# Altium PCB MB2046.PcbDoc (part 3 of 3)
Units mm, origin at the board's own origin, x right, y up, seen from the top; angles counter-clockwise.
Board outline 70 x 82.5 mm, 2 copper layers (Top Layer, Bottom Layer), stack 1.47 mm thick; 179 components, 148 nets, 719 pads, 862 vias.
Unrouted connection lines stored in the file: 135.
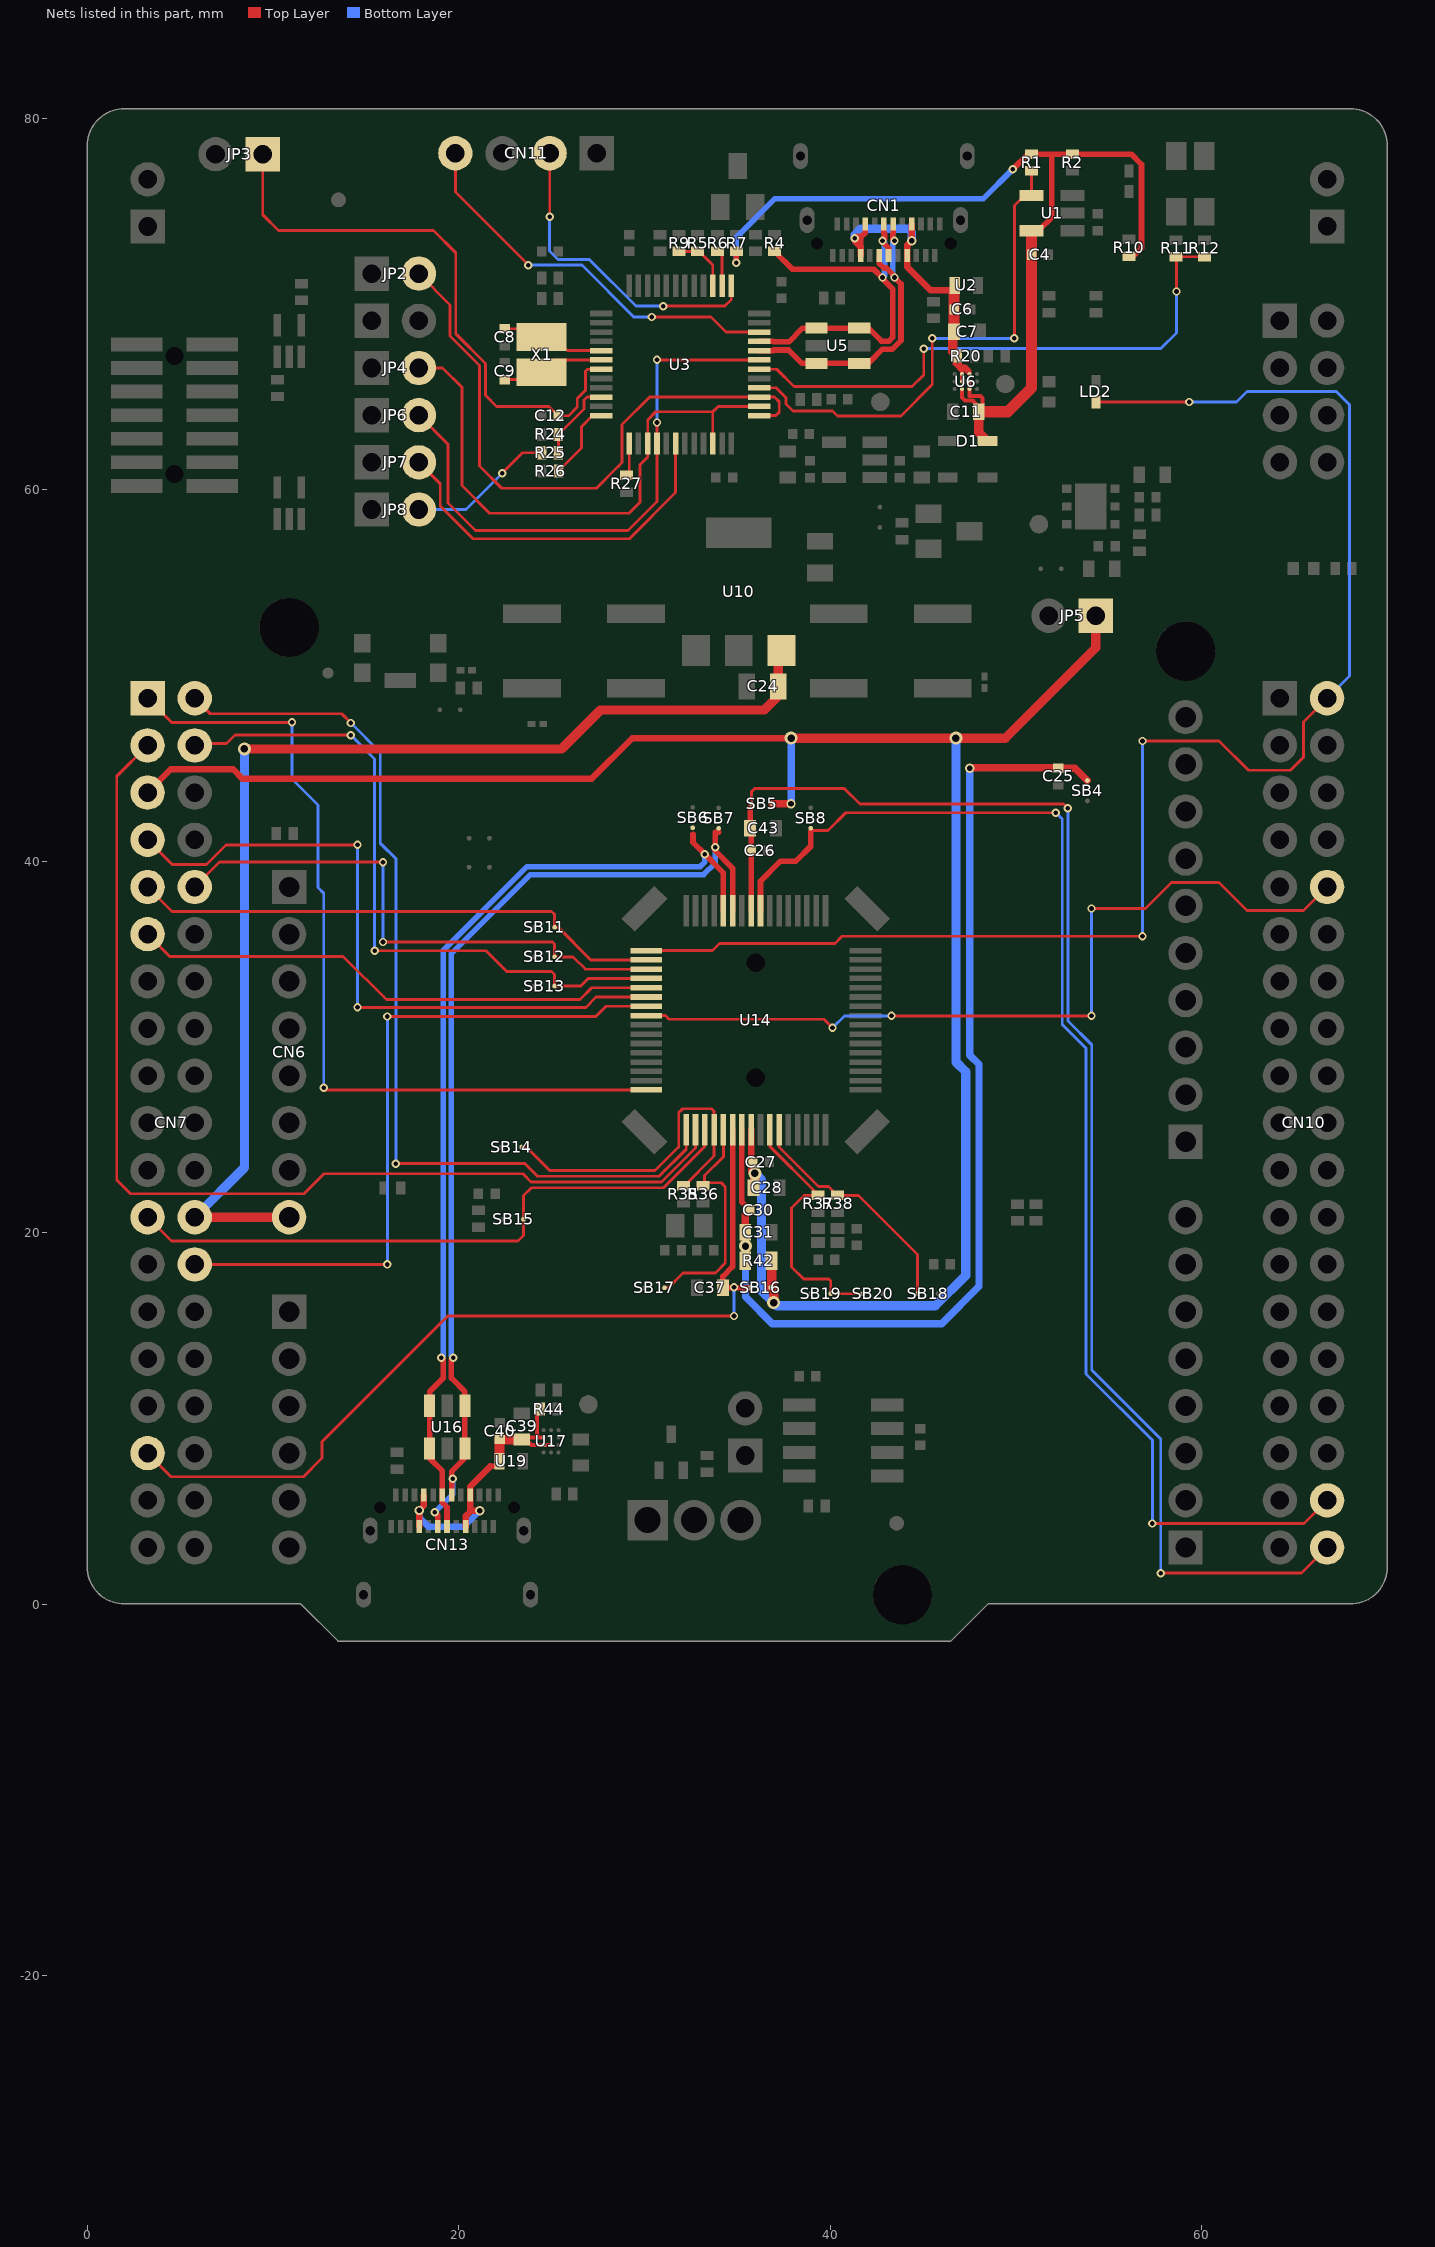
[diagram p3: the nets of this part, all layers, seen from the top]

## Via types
v1: diameter 0.45, hole 0.25, Top Layer to Bottom Layer, tented both sides, 830 vias
v2: diameter 0.7, hole 0.4, Top Layer to Bottom Layer, tented both sides, 21 vias
v3: diameter 0.5, hole 0.3, Top Layer to Bottom Layer, tented both sides, 11 vias

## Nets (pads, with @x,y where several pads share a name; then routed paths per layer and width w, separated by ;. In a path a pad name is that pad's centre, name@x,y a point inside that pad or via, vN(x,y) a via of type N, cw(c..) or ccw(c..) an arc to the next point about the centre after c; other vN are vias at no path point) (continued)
PC9: CN10.2 LD2.2 U14.49 | length 81.3
  Top Layer w0.152: U14.49@30.099,35.183 33.658,35.183 34.042,35.568 40.255,35.568 40.645,35.957 v1(56.813,35.957) ; LD2.2@54.305,64.708 59.318,64.708 v1(59.327,64.718) ; v1@56.818,46.467 60.933,46.467 62.51,44.89 64.778,44.89 65.48,45.592 65.48,47.497 CN10.2@66.751,48.768
  Bottom Layer w0.152: v1(56.813,35.957) v1(56.813,46.467) ; v1(59.327,64.718) 61.873,64.718 62.435,65.28 67.243,65.28 67.954,64.568 67.954,49.971 CN10.2@66.751,48.768
PC10: CN7.1 U14.64 | length 46.2
  Top Layer w0.152: CN7.1@3.251,48.768 4.554,47.465 v1@11.027,47.465 ; v1(12.729,27.8) 12.846,27.683 U14.64@30.099,27.683
  Bottom Layer w0.152: v1(11.027,47.477) 11.027,44.415 12.431,43.012 12.431,38.572 12.736,38.267 12.736,27.807 v1(12.729,27.8) v1@12.693,27.8
PC11: CN7.2 U14.1 | length 51.2
  Top Layer w0.152: CN7.2@5.791,48.768 6.628,47.931 13.702,47.931 v1(14.198,47.435) ; v1(16.618,23.714) 23.558,23.715 24.241,23.032 30.791,23.032 32.249,24.49 U14.1@32.249,25.533
  Bottom Layer w0.152: v1(14.198,47.435) 15.779,45.853 15.779,40.966 16.618,40.128 v1(16.618,23.714)
PC12: CN7.3 U14.2 | length 57.9
  Top Layer w0.152: CN7.3@3.251,46.228 1.593,44.569 1.593,22.835 2.332,22.095 11.668,22.095 12.74,23.168 23.463,23.168 23.902,22.728 30.917,22.728 32.749,24.559 U14.2@32.749,25.533
PC13: CN7.23 SB15.2 U14.3 | length 34.8
  Top Layer w0.152: CN7.23@3.251,20.828 4.532,19.547 23.2,19.547 23.49,19.837 SB15.2@23.49,20.72 23.49,21.992 23.912,22.415 31.035,22.415 33.249,24.629 U14.3@33.249,25.533
PC14: R35.2 SB14.1 U14.4 | length 18.1
  Top Layer w0.152: SB14.1@23.39,24.605 23.635,24.605 24.904,23.336 30.574,23.336 31.842,24.605 31.842,26.45 32.064,26.671 33.609,26.671 33.749,26.531 U14.4@33.749,25.533 33.749,24.121 R35.2@32.142,22.514
PC15: R36.2 SB17.1 U14.5 | length 12.6
  Top Layer w0.152: SB17.1@31.083,17.03 31.283,17.03 32.085,17.832 33.825,17.832 34.352,18.36 34.352,22.465 34.135,22.682 33.403,22.682 33.234,22.514 33.234,23.072 34.249,24.086 U14.5@34.249,25.533
PD0: CN7.9 SB11.1 U14.50 | length 28.9
  Top Layer w0.152: CN7.9@3.251,38.608 4.564,37.295 25.005,37.295 25.163,37.137 SB11.1@25.163,36.436 25.359,36.436 27.112,34.683 U14.50@30.099,34.683
PD1: CN7.10 SB12.1 U14.51 | length 30.3
  Top Layer w0.152: CN7.10@5.791,38.608 7.128,39.945 v1(15.928,39.945) ; v1@15.929,35.642 25.048,35.642 25.163,35.527 SB12.1@25.163,34.846 26.157,34.846 26.819,34.183 U14.51@30.099,34.183
  Bottom Layer w0.152: v1@15.809,35.643 v1(15.928,35.643) v1(15.928,39.945)
PD2: CN7.4 SB13.1 U14.52 | length 36.8
  Top Layer w0.152: CN7.4@5.791,46.228 5.791,46.328 7.496,46.328 7.95,46.782 v1(14.19,46.782) ; v1(15.475,35.177) 21.473,35.177 22.59,34.06 25.003,34.06 25.163,33.899 SB13.1@25.163,33.274 26.569,33.274 26.978,33.683 U14.52@30.099,33.683
  Bottom Layer w0.152: v1(14.19,46.782) 15.475,45.497 v1(15.475,35.177)
PD3: CN7.11 U14.53 | length 28.6
  Top Layer w0.152: CN7.11@3.251,36.068 4.446,34.873 13.779,34.873 16.107,32.546 26.526,32.546 27.163,33.183 U14.53@30.099,33.183
PD4: CN7.7 U14.54 | length 36.8
  Top Layer w0.152: CN7.7@3.251,41.148 4.582,39.817 6.418,39.817 7.473,40.873 14.557,40.873 v1@14.556,40.875 ; v1(14.556,32.127) 26.845,32.127 27.401,32.683 U14.54@30.099,32.683
  Bottom Layer w0.152: v1(14.556,32.127) v1@14.556,40.875
  other v1: 14.556,40.873
PD5: CN7.26 U14.55 | length 37.9
  Top Layer w0.152: CN7.26@5.791,18.288 v1(16.161,18.288) ; v1(16.161,31.637) 27.377,31.637 27.923,32.183 U14.55@30.099,32.183
  Bottom Layer w0.152: v1(16.161,18.288) v1(16.161,31.637)
PD6: CN10.10 U14.56 | length 44.8
  Top Layer w0.152: U14.56@30.099,31.683 31.134,31.683 31.33,31.488 39.67,31.488 v1(40.127,31.03) ; v1(43.302,31.668) 53.438,31.667 ; 53.462,31.668 v1(54.066,31.667) ; v1(54.067,37.453) 56.973,37.453 58.37,38.85 60.922,38.85 62.438,37.335 65.478,37.335 CN10.10@66.751,38.608
  Bottom Layer w0.152: v1(40.127,31.03) 40.765,31.668 v1(43.302,31.668) ; v1@54.066,37.452 v1(54.066,31.667) v1@54.189,31.667
PD8: CN10.36 SB8.1 U14.40 | length 69.9
  Top Layer w0.152: 38.955,41.607 38.955,41.652 39.885,41.652 40.837,42.605 v1(52.148,42.605) ; CN10.36@66.751,5.588 65.506,4.343 v1@57.339,4.343 ; v1(57.338,4.341) v1@57.339,4.343
  Top Layer w0.3: U14.40@36.249,37.333 36.249,38.914 37.331,39.996 38.151,39.996 38.955,40.801 38.955,41.607
  Bottom Layer w0.152: v1(52.148,42.605) 52.493,42.26 52.493,31.21 53.774,29.928 53.774,12.398 57.349,8.823 57.349,4.33 v1(57.338,4.341)
PD9: C26.2 C43.2 CN10.38 SB5.1 U14.41 | length 77.8
  Top Layer w0.152: C43.2@35.575,41.577 C43.2@35.749,41.403 ; 35.755,42.962 35.755,43.733 35.94,43.917 40.755,43.917 41.602,43.07 52.561,43.07 v1(52.794,42.837) ; v1(57.793,1.667) 65.371,1.667 CN10.38@66.751,3.048
  Top Layer w0.3: U14.41@35.749,37.333 C43.2@35.749,41.363 ; C26.2@35.75,40.57 35.75,41.71 C43.2@35.69,41.77 35.69,42.897 35.755,42.962
  Bottom Layer w0.152: v1(52.794,42.837) 52.797,42.834 52.797,31.393 54.079,30.111 54.079,12.596 57.793,8.882 v1(57.793,1.667)
PF0: R37.2 SB19.1 SB20.2 U14.10 | length 14.4
  Top Layer w0.152: U14.10@36.749,25.533 36.749,24.648 R37.2@39.217,22.181 ; R37.2@39.261,22.181 39.44,22.002 R37.2@39.35,22.002 38.584,22.002 37.918,21.335 37.918,18.152 38.575,17.495 39.925,17.495 40.033,17.388 SB19.1@40.033,16.712 41.723,16.712 SB20.2@41.73,16.705
PF1: R38.2 SB18.1 U14.11 | length 12.9
  Top Layer w0.152: U14.11@37.249,25.533 37.249,24.601 39.365,22.485 39.916,22.485 R38.2@40.4,22.002 41.53,22.002 44.708,18.825 SB18.1@44.708,16.718
PF3/VBAT: C37.1 CN7.33 SB16.2 U14.6 | length 47.7
  Top Layer w0.152: CN7.33@3.251,8.128 4.519,6.86 11.637,6.86 12.645,7.868 12.645,8.74 19.415,15.51 v1(34.82,15.51)
  Top Layer w0.3: C37.1@34.225,17.043 34.225,17.645 34.749,18.169 U14.6@34.749,25.533 ; C37.1@34.431,17.043 SB16.2@35.697,17.043
  Bottom Layer w0.152: v1(34.82,15.51) v1(34.82,17.05)
STLK_LED: R11.1 R12.2 U3.30 | length 30.5
  Top Layer w0.12: R11.1@58.623,72.533 R12.2@60.147,72.533
  Top Layer w0.152: U3.30@36.178,66.482 37.12,66.482 38.06,65.543 44.408,65.543 45.037,66.172 v1(45.037,67.59) ; R11.1@58.623,72.533 58.642,72.514 v1(58.642,70.663)
  Bottom Layer w0.152: v1(45.037,67.59) 57.797,67.59 58.642,68.435 v1(58.642,70.663)
STLK_NRST: C12.2 JP3.1 U3.7 | length 31.4
  Top Layer w0.152: JP3.1@9.45,78.058 9.45,74.8 10.292,73.958 18.637,73.958 19.842,72.753 19.842,68.394 21.439,66.796 21.439,65.078 22.037,64.48 24.862,64.48 C12.2@25.371,63.972 25.907,63.972 26.382,64.448 26.382,64.902 26.832,65.352 26.832,66.367 26.947,66.482 U3.7@27.678,66.482
STLK_OSC_IN: C8.2 U3.5 X1.2 | length 5.7
  Top Layer w0.152: C8.2@22.477,68.656 24.02,68.656 X1.2@24.46,68.216 25.046,67.63 25.702,67.63 25.85,67.482 U3.5@27.678,67.482
STLK_OSC_OUT: C9.1 U3.6 X1.1 | length 5.6
  Top Layer w0.152: C9.1@22.477,65.927 24.071,65.927 X1.1@24.46,66.316 25.127,66.982 U3.6@27.678,66.982
STLK_SWCLK: CN11.2 U3.37 | length 17.2
  Top Layer w0.152: v1@24.9,74.698 CN11.2@24.9,78.108 ; v1(31.013,69.88) 34.322,69.88 34.678,70.235 U3.37@34.678,70.982
  Bottom Layer w0.152: v1(24.895,74.698) 24.895,72.846 25.351,72.389 27.031,72.389 29.54,69.88 v1(31.013,69.88)
STLK_SWDIO: CN11.4 U3.34 | length 21.6
  Top Layer w0.152: CN11.4@19.82,78.108 19.82,76.017 v1(23.753,72.085) ; v1(30.385,69.293) 33.58,69.293 34.39,68.482 U3.34@36.178,68.482
  Bottom Layer w0.152: v1(23.753,72.085) 26.632,72.085 29.425,69.293 v1(30.385,69.293)
STLK_USB_N: CN1.A7 CN1.B7 U3.32 U5.3 U5.4 | length 16.6
  Top Layer w0.3: U3.32@36.178,67.482 36.928,67.482 36.961,67.515 37.765,67.515 38.488,66.792 U5.3@39.261,66.792 U5.4@41.561,66.792 42.047,66.792 42.817,67.562 43.346,67.562 43.811,68.028 43.811,71.074 v1(43.465,71.42) 43.465,71.49 43.026,71.929 42.893,71.929 42.64,72.182 CN1.A7@42.64,72.598 ; CN1.B7@43.39,74.298 43.39,73.798 43.357,73.765 43.357,73.503 v1(43.465,73.395)
  Bottom Layer w0.3: v1(43.465,71.42) 43.357,71.528 43.357,73.287 v1(43.465,73.395)
STLK_USB_P: CN1.A6 CN1.B6 R4.1 U3.33 U5.1 U5.6 | length 21.7
  Top Layer w0.3: U3.33@36.178,67.982 36.928,67.982 36.961,67.949 37.772,67.949 38.514,68.692 U5.1@39.261,68.692 U5.6@41.561,68.692 42.056,68.692 42.751,67.996 43.166,67.996 43.378,68.207 43.378,70.788 42.815,71.35 v1(42.815,71.42) 42.789,71.42 42.344,71.865 37.964,71.865 R4.1@37.008,72.821 ; CN1.B6@42.89,74.298 42.89,73.798 42.923,73.765 42.923,73.503 v1(42.815,73.395) 42.815,73.325 43.14,73 CN1.A6@43.14,72.598
  Bottom Layer w0.3: v1(42.815,71.42) 42.923,71.528 42.923,73.287 v1(42.815,73.395)
STLK_VCP_RX: R27.1 U3.13 | length 1.9
  Top Layer w0.152: R27.1@29.178,60.586 U3.13@29.178,62.482
STLK_VCP_TX: R26.1 U3.12 | length 4.2
  Top Layer w0.152: R26.1@25.375,60.998 26.61,62.232 26.61,63.387 27.205,63.982 U3.12@27.678,63.982
T_NRST: JP7.2 U3.18 | length 19.9
  Top Layer w0.152: JP7.2@17.856,61.468 19.01,60.315 19.01,59.115 20.773,57.352 29.188,57.352 31.678,59.843 U3.18@31.678,62.482
T_PWR_EN: R1.1 U1.4 U3.28 | length 27.4
  Top Layer w0.152: U3.28@36.178,65.482 37.088,65.482 37.623,64.948 37.623,64.605 37.99,64.237 40.12,64.237 40.395,63.963 43.803,63.963 45.495,65.655 v1(45.495,68.14) ; v1(49.917,68.14) 49.917,75.29 50.466,75.838 U1.4@50.843,75.838 R1.1@50.843,77.156
  Bottom Layer w0.152: v1(45.495,68.14) v1(49.917,68.14)
T_PWR_EXT: R5.1 R9.1 U3.39 | length 3.3
  Top Layer w0.152: R9.1@31.763,72.82 32.95,72.82 33.678,72.092 U3.39@33.678,70.982
T_SWCLK: JP4.2 U3.15 U3.22 U3.26 | length 31.1
  Top Layer w0.152: JP4.2@17.856,66.548 19.137,66.548 20.172,65.513 20.172,60.215 21.66,58.728 29.173,58.728 29.767,59.322 29.767,61.34 30.178,61.75 U3.15@30.178,62.482 30.178,63.757 30.611,64.19 33.678,64.19 ; U3.22@33.678,62.482 33.678,64.19 ; U3.26@36.178,64.482 33.97,64.482 33.678,64.19
T_SWDIO: JP2.2 U3.25 U3.27 | length 33.4
  Top Layer w0.152: JP2.2@17.856,71.628 19.537,69.947 19.537,68.268 21.12,66.685 21.12,61.265 22.315,60.07 27.41,60.07 28.447,61.107 28.447,61.115 28.58,61.248 28.588,61.248 28.8,61.46 28.8,61.787 ; 28.799,61.788 28.799,63.497 30.285,64.982 U3.27@36.178,64.982 37.005,64.982 37.255,64.732 37.255,64.167 37.07,63.982 U3.25@36.178,63.982
T_SWO: JP6.2 U3.16 U3.31 | length 31.1
  Top Layer w0.152: JP6.2@17.856,64.008 19.42,62.444 19.42,59.285 20.912,57.793 29.12,57.793 30.678,59.351 30.678,61.512 ; v1(30.675,63.613) 30.675,62.485 U3.16@30.678,62.482 30.678,61.513 ; v1@30.678,66.982 U3.31@36.178,66.982
  Bottom Layer w0.152: v1@30.678,63.513 v1(30.678,66.998)
T_VCC: JP8.2 R25.2 | length 7.9
  Top Layer w0.152: v1(22.353,60.885) 22.353,60.904 23.433,61.984 R25.2@24.471,61.984
  Bottom Layer w0.152: JP8.2@17.856,58.928 20.396,58.928 v1(22.353,60.885)
T_VCC_AIN: R24.1 R25.1 U3.10 | length 4.5
  Top Layer w0.152: R25.1@25.371,61.914 R25.1@25.371,61.984 R24.1@25.371,62.972 26.745,64.346 26.745,64.818 26.91,64.982 U3.10@27.678,64.982
USB.D_N: CN13.A7 CN13.B7 SB7.2 U14.43 U16.3 U16.4 | length 54.8
  Top Layer w0.3: v1(18.72,4.953) 18.871,4.802 CN13.B7@18.871,4.168 ; CN13.A7@19.621,5.868 19.621,7.15 20.337,7.865 U16.3@20.337,8.382 U16.4@20.337,10.682 20.337,11.432 19.604,12.165 19.604,13.165 v1(19.712,13.273) ; 34.01,41.553 33.817,41.553 v1(33.817,40.738) 33.817,40.549 34.749,39.617 U14.43@34.749,37.333
  Bottom Layer w0.3: v1(18.72,4.953) 19.685,5.918 v1(19.685,6.756) ; v1(19.712,13.273) 19.604,13.381 19.604,35.017 23.86,39.274 33.183,39.274 33.817,39.909 v1(33.817,40.738)
USB.D_P: CN13.A6 CN13.B6 SB6.2 U14.44 U16.1 U16.6 | length 53.1
  Top Layer w0.3: v1(19.062,13.273) 19.17,13.165 19.17,12.165 18.437,11.432 U16.6@18.437,10.682 U16.1@18.437,8.382 18.437,7.852 19.121,7.168 CN13.A6@19.121,5.868 19.121,5.466 19.371,5.216 CN13.B6@19.371,4.168 ; 32.613,41.458 32.613,41.007 v1(33.252,40.368) 34.249,39.371 U14.44@34.249,37.333
  Bottom Layer w0.3: v1(19.062,13.273) 19.17,13.381 19.17,35.197 23.681,39.708 33.003,39.708 33.252,39.957 v1(33.252,40.368)
USB_RENUMn: R6.2 U3.38 | length 1.9
  Top Layer w0.152: R6.2@33.934,72.821 34.178,72.577 U3.38@34.178,70.982
VBUS: C6.1 C7.1 CN1.A4 CN1.A9 CN1.B4 CN1.B9 R20.2 U2.1 U6.B3 U6.C2 U6.C3 | length 20.1
  Top Layer w0.22: U6.B3@47.101,65.818 U6.C3@47.101,66.218 47.101,66.362 46.708,66.755 46.708,67.042 R20.2@46.854,67.188 46.998,67.044 46.998,66.721 47.094,66.624 ; 47.094,66.624 47.293,66.624 47.501,66.417 U6.C2@47.501,66.218 47.094,66.624
  Top Layer w0.3: 41.633,73.071 41.633,73.079 41.633,73.58 ; CN1.A9@41.64,72.598 41.64,73.071 ; 41.64,73.58 41.685,73.625 41.89,73.83 41.89,73.851 ; 41.685,73.646 41.89,73.851 ; CN1.B4@41.89,74.298 41.89,73.851
  Top Layer w0.33: v1(41.325,73.53) 41.42,73.625 41.685,73.625
  Top Layer w0.35: v1(41.325,73.53) 41.325,73.386 41.633,73.079 41.64,73.071 ; CN1.A9@41.64,72.598 41.64,73.071 ; CN1.B9@44.39,74.298 v3(44.39,73.395) 44.14,73.145 CN1.A4@44.14,72.598 44.14,72 45.415,70.725 U2.1@46.671,70.725
  Top Layer w0.5: C7.1@46.671,68.566 46.604,68.498 46.604,67.438 R20.2@46.854,67.188
  Top Layer w0.6: C7.1@46.671,68.566 C6.1@46.671,69.698 U2.1@46.671,70.725
  Bottom Layer w0.45: v1(41.325,73.53) 41.325,73.733 41.637,74.045 44.202,74.045 44.39,73.857 v3(44.39,73.395)
VBUS2: C39.1 C40.1 CN13.A4 CN13.A9 CN13.B4 CN13.B9 R44.2 U17.B3 U17.C2 U17.C3 U19.1 | length 17.9
  Top Layer w0.2: 24.155,8.966 24.215,9.025 24.215,10.308 R44.2@24.398,10.492 R44.2@24.398,10.343
  Top Layer w0.22: C39.1@23.4,8.865 23.622,8.865 23.92,8.566 U17.C3@24.575,8.566 U17.B3@24.975,8.566 ; C39.1@23.501,8.966 24.155,8.966 U17.C2@24.575,8.966
  Top Layer w0.3: 21.707,7.417 22.013,7.417 U19.1@22.2,7.604
  Top Layer w0.35: CN13.B9@17.871,4.168 v3(17.871,5.044) 18.121,5.294 CN13.A4@18.121,5.868 ; CN13.B4@20.371,4.168 20.371,4.725 20.621,4.975 20.621,5.156 ; v3(21.133,5.029) 20.748,5.029 20.621,5.156 ; 21.707,7.417 20.621,6.331 CN13.A9@20.621,5.868 20.621,5.156
  Top Layer w0.5: U19.1@22.2,7.604 U19.1@22.2,7.696
  Top Layer w0.55: U19.1@22.2,7.696 C40.1@22.2,8.788 ; C40.1@22.2,8.865 C39.1@23.4,8.865
  Bottom Layer w0.35: v3(17.871,5.044) 17.871,4.668 18.371,4.168 20.272,4.168 v3(21.133,5.029)
VBUS_STLK: C4.2 C11.2 D1.1 R1.2 R2.2 R7.2 R10.2 U1.5 U6.A2 U6.A3 U6.B2 | length 53.3
  Top Layer w0.22: U6.A3@47.101,65.418 47.101,64.959 47.26,64.8 47.673,64.8 47.996,64.476 C11.2@47.996,64.195 ; 47.501,65.038 48.092,65.038 ; 47.501,65.048 U6.A2@47.501,65.418 U6.B2@47.501,65.818 ; 48.098,65.028 48.202,64.923 C11.2@48.202,64.598
  Top Layer w0.3: v1(34.95,72.205) 34.953,72.202 34.953,72.815 R7.2@34.959,72.821 ; v1(49.828,77.245) 50.639,78.056 R1.2@50.843,78.056 51.93,78.056 ; U1.5@50.843,73.938 51.223,73.938 51.93,74.645 51.93,78.056 ; R10.2@56.083,72.575 56.325,72.575 56.757,73.007 56.757,77.51 56.211,78.056 R2.2@53.043,78.056 51.93,78.056
  Top Layer w0.5: C11.2@47.996,64.195 47.996,63.08 D1.1@48.465,62.611
  Top Layer w0.6: C11.2@47.996,64.195 49.56,64.195 50.843,65.478 C4.2@50.843,72.65 U1.5@50.843,73.938
  Bottom Layer w0.3: v1(34.95,72.205) 34.95,73.587 37.025,75.663 48.245,75.663 v1(49.828,77.245)
VDD: C27.2 C28.2 CN7.5 JP5.1 R42.1 SB5.2 SB16.1 U14.8 | length 113.8
  Top Layer w0.35: CN7.5@3.251,43.688 4.504,44.94 7.86,44.94 8.355,44.445 8.705,44.445 27.17,44.445 29.34,46.615 v2(37.892,46.615) ; C27.2@35.749,23.8 U14.8@35.749,25.533
  Top Layer w0.4: SB5.2@36.873,43.095 v3(37.892,43.095)
  Top Layer w0.5: C27.2@35.821,23.8 35.821,23.31 v2(35.941,23.19) C28.2@35.941,22.481 ; SB16.1@36.797,17.043 36.849,17.095 36.849,18.456 36.797,18.456 R42.1@36.83,18.489 ; v2(36.958,16.228) 36.958,16.882 ; v2(37.892,46.615) v2(46.768,46.615) 49.43,46.615 54.3,51.485 JP5.1@54.3,53.208
  Bottom Layer w0.4: v3(37.892,43.095) v2(37.892,46.615)
  Bottom Layer w0.5: v2(35.941,23.19) 36.303,22.828 36.303,16.883 v2(36.958,16.228) 37.123,16.063 45.663,16.063 47.29,17.69 47.29,28.66 46.768,29.182 v2(46.768,46.615)
VIN: C24.2 CN6.8 CN7.24 U10.3 | length 63.5
  Top Layer w0.5: CN7.24@5.791,20.828 CN6.8@10.871,20.828 ; v2(8.467,46.04) 25.54,46.04 27.632,48.132 36.45,48.132 37.21,48.892 C24.2@37.21,49.41 37.21,50.88 U10.3@37.377,51.047
  Bottom Layer w0.5: CN7.24@5.791,20.828 8.467,23.504 v2(8.467,46.04)
VREFP: C25.1 C30.2 C31.1 R42.2 SB4.2 U14.7 | length 58.8
  Top Layer w0.3: U14.7@35.249,25.533 35.249,21.647 C30.2@35.68,21.216
  Top Layer w0.4: R42.2@35.43,18.489 C31.1@35.43,20.016 35.43,20.966 C30.2@35.68,21.216 ; v3@47.507,45.03 52.265,45.03 C25.1@52.285,45.01 53.177,45.01 SB4.2@53.847,44.34
  Bottom Layer w0.4: v2(35.44,19.278) 35.44,16.54 36.875,15.105 46.008,15.105 48.01,17.107 48.01,29.055 47.507,29.558 v3(47.507,45)
pads on no net: CN1.0 CN1.A2 CN1.A3 CN1.A8 CN1.A10 CN1.A11 CN1.B2 CN1.B3 CN1.B8 CN1.B10 CN1.B11 CN4.0 CN4.1 CN4.2 CN4.10 CN13.0 CN13.A2 CN13.A3 CN13.A8 CN13.A10 CN13.A11 CN13.B2 CN13.B3 CN13.B8 CN13.B10 CN13.B11 HW9.1 HW10.1 HW16.1 HW17.1 U3.4 U3.11 U3.14 U3.17 U3.19 U3.21 U3.40 U3.41 U3.42 U3.43 U3.45 U3.46 U5.5 U14.0 U16.5

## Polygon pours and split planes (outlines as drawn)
GND on Top Layer "DEFAULT" (solid, remove dead copper, pour order 0): 0.001,2.006 ccw(c2.001,2.006) 2.001,0.006 11.501,0.006 13.501,-1.994 46.501,-1.994 48.501,0.006 68.001,0.006 ccw(c68.001,2.006) 70.001,2.006 70.001,78.506 ccw(c68.001,78.506) 68.001,80.506 2.001,80.506 ccw(c2.001,78.506) 0.001,78.506
GND on Bottom Layer "DEFAULT" (solid, remove dead copper, pour order 2): 0.001,2.006 ccw(c2.001,2.006) 2.001,0.006 11.501,0.006 13.501,-1.994 46.501,-1.994 48.501,0.006 68.001,0.006 ccw(c68.001,2.006) 70.001,2.006 70.001,78.506 ccw(c68.001,78.506) 68.001,80.506 2.001,80.506 ccw(c2.001,78.506) 0.001,78.506

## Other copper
Top Layer:
  pour cut-out: 57.616,50.16 56.733,47.752 56.318,46.672 55.864,45.416 55.409,44.179 55.409,43.268 58.05,43.268 58.05,50.16
  pour cut-out: 58.378,7.409 56.674,7.409 56.36,7.095 56.36,2.4 57.588,1.173 58.053,1.173 58.378,1.498
  pour cut-out: 38.45,56.654 38.45,56.107 38.48,56.078 38.517,56.115 39.45,56.115 39.45,56.53 39.588,56.667
  pour cut-out: 33.403,52.407 33.403,50.385 33.567,50.22 36.363,50.22 36.905,50.762 36.905,52.258 36.755,52.407
  pour cut-out: 12.076,40.133 12.078,40.133 12.078,19.304
  region net VBUS: 46.942,70.892 45.175,70.892 44.14,71.927 46.538,71.927 46.975,71.49 46.975,70.925
  region net VBUS_STLK: 48.071,65.145 47.012,65.145 47.357,64.8 47.673,64.8 47.996,64.476 48.081,64.476 48.202,64.598
  region net VBUS: 46.357,67.02 46.357,66.63 46.497,66.49 47.2,66.49 47.2,66.54 46.748,66.992 46.748,67.02
  region net VBUS: 46.932,68.115 47.103,67.945 47.102,66.815 47.21,66.707 47.33,66.707 47.39,66.653 47.39,66.515 47.357,66.483 46.942,66.483 46.942,66.643 46.645,66.94 46.645,68.027 46.732,68.115
  region net VBUS: 46.357,68.443 46.357,66.95 46.645,66.663 46.704,66.721 46.998,66.721 46.92,66.799 46.92,68.182 46.658,68.443
  region net VBUS: 47.101,66.295 47.37,66.295 47.453,66.377 47.367,66.463 47.115,66.47 47.098,66.453
  region net VBUS: 46.715,67.125 46.715,66.74 46.95,66.505 47.05,66.605 47.075,66.605 47.075,66.902 46.91,67.067 46.91,67.105
  region net 5V_USB: 26.235,9.185 25.792,9.185 25.64,9.033 25.64,8.872 25.735,8.872 25.865,8.742 26.267,8.742 26.452,8.928
  region net VBUS2: 23.745,9.182 24.215,9.182 24.215,9.025 24.181,8.992 23.8,8.992
  region net 5V_USB: 26.276,8.966 25.634,8.966 25.634,8.566 26.276,8.566
  region net VBUS2: 24.333,8.992 24.333,8.636 24.263,8.566 23.92,8.566 23.8,8.687 23.8,8.992
  region net VBUS2: 22.135,8.09 22.479,7.747 22.479,7.2 21.781,6.502 20.618,6.502 20.582,6.537
  text "1" at 2.631,52.08 h2.5 r90
  text ".Layer_Name" at -0.27,-24.55 h3
  text ".GTL" at 41.424,-24.55 h3
Bottom Layer:
  pour cut-out: 57.611,50.16 56.728,47.752 56.313,46.672 55.859,45.416 55.526,44.512 55.526,43.268 58.045,43.268 58.045,50.16
  text "2" at 2.631,56.031 h2.5 r90
  text ".GBL" at 30.221,-24.582 h3
  text ".Layer_Name" at 71.535,-24.582 h3
Multi-Layer:
  pour cut-out: 0.431,51.33 3.431,51.33 3.431,56.713 0.431,56.713
  pour cut-out: 33.363,25.252 33.362,24.86 30.183,21.68 30.183,18.273 30.612,17.842 33.92,17.842 34.515,18.437 34.515,26.508 34.433,26.589 33.442,26.585 33.362,26.505 33.363,25.252 33.595,25.252 33.595,26.168 33.733,26.305 34.213,26.305 34.32,26.198 34.32,23.975 34.185,23.84 34.185,18.635 33.687,18.137 30.838,18.137 30.51,18.465 30.51,21.515 33.595,24.6 33.595,25.252
  pour cut-out: 68.051,78.018 68.051,72.858 65.451,72.858 65.451,78.018
  pour cut-out: 28.75,76.808 18.51,76.808 18.51,79.408 28.75,79.408
  pour cut-out: 1.955,72.853 1.955,78.013 4.555,78.013 4.555,72.853
  pour cut-out: 5.6,79.358 10.76,79.358 10.76,76.758 5.6,76.758
  pour cut-out: 55.61,54.508 50.45,54.508 50.45,51.908 55.61,51.908
  pour cut-out: 62.94,70.363 62.94,60.203 68.02,60.203 68.02,70.363
  pour cut-out: 19.02,72.955 18.993,72.928 14.006,72.928 14.006,57.628 19.166,57.628 19.166,72.928
  pour cut-out: 26.923,68.387 26.93,68.893 25.937,69.885 22.11,69.885 21.465,69.24 21.465,65.26 22.038,64.688 26.11,64.688 26.858,65.435 26.858,66.41 27.032,66.585 28.32,66.585 28.58,66.845 28.58,68.452 28.24,68.793 26.925,68.792 26.925,68.387 27.981,68.387 28.235,68.133 28.235,67.01 28.113,66.888 26.867,66.887 26.572,66.592 26.573,65.61 25.99,65.027 22.248,65.028 21.807,65.467 21.808,69.083 22.261,69.536 25.781,69.529
  pour cut-out: 38.072,21.916 38.072,18.288 38.715,17.645 41.34,17.645 42.365,18.67 42.365,20.747 40.212,22.9 39.801,22.9 37.649,25.052 37.649,26.416 37.402,26.662 36.535,26.663 36.388,26.516 36.388,24.454 38.072,22.77 38.072,21.907 38.42,21.907 38.42,22.87 36.649,24.641 36.649,26.383 37.349,26.383 37.402,26.33 37.402,24.795 39.553,22.645 40.056,22.645 41.972,20.729 41.973,18.778 41.165,17.97 38.888,17.97 38.42,18.438 38.42,21.909
  pour cut-out: 57.925,23.368 60.338,23.368 60.338,49.277 57.927,49.277
  pour cut-out: 60.338,22.354 57.926,22.353 57.926,1.524 60.338,1.524
  pour cut-out: 68.021,50.038 62.941,50.038 62.941,1.778 68.021,1.778
  pour cut-out: 12.078,17.272 9.666,17.272 9.666,1.524 12.078,1.524 12.078,17.273 12.076,17.273
  pour cut-out: 9.665,19.304 12.078,19.304 12.078,40.133 9.666,40.133
  pour cut-out: 7.061,50.038 1.981,50.038 1.981,1.778 7.061,1.778

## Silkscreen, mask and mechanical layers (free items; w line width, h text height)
Top Overlay:
  circle w0.127: c53.236,49.995 r1.42
  circle w0.127: c50.442,50.045 r0.203
  circle w0.127: c55.852,49.995 r0.209
  lines w0.152: 50.442,50.045 51.814,50.045 ; 54.656,49.995 55.852,49.995
  lines w0.25: 58.649,54.94 69.573,54.94 69.573,71.341 58.649,71.341 58.649,54.94
  lines w0.254: 50.353,61.725 50.353,71.341 58.651,71.341 58.651,61.725 ; 50.353,61.725 58.651,61.725
  text "COM" at 58.039,79.146 h1.5
  text "GND" at 65.354,78.443 h1.52
  text "GND" at 1.853,78.414 h1.52
  text "USB STLINK" at 29.657,77.42 h1.52
  text "STLK RST" at 11.608,77.046 h1.52
  text "RESERVED" at 20.195,75.615 h1.5
  text "MIPI10" at 2.692,70.714 h1.5
  text "STLK" at 59.334,68.631 h1.5
  text "VIN" at 60.274,66.116 h1.5
  text "MCO" at 41.768,65.47 h1.5
  text "EXT" at 60.071,63.551 h1.5
  text "User LEDS" at 51.333,62.103 h1.5
  text "5V_SELECT" at 69.19,61.544 h1.4 r90
  text "USB" at 60.067,60.885 h1.5
  text "5V" at 66.148,59.037 h1.4
  text "PWR_ON" at 63.321,56.775 h1.4
  text "USER" at 25.044,54.889 h1.5
  text "RESET" at 41.097,54.864 h1.5
  text "VDD MCU" at 47.695,52.225 h1.4
  text "A" at 52.499,49.275 h2.54
  text "SCL" at 55.718,48.031 h1.14
  text "BOOT" at 14.057,47.942 h1.5
  text "IDD" at 52.245,47.161 h1.5
  text "D15" at 55.168,46.806 h1.02
  text "SDA" at 55.568,45.714 h1.14
  text "D14" at 55.121,44.418 h1.02
  text "AREF" at 54.858,42.205 h0.84
  text "GND" at 54.904,39.846 h1.02
  text "SCK" at 55.571,38.449 h1.14
  text "NC" at 12.421,38.049 h1.5
  text "D13" at 55.46,37.306 h0.89
  text "MISO" at 55.133,36.087 h1.14
  text "IOREF" at 12.395,35.56 h1.5
  text "D12" at 55.46,34.995 h0.89
  text "PWM" at 55.281,33.776 h1.14
  text "MOSI" at 55.179,32.887 h1.14
  text "NRST" at 12.395,32.766 h1.5
  text "D11" at 55.841,31.82 h0.89
  text "PWM" at 55.281,30.728 h1.14
  text "3V3" at 12.395,30.48 h1.5
  text "CS" at 56.308,29.788 h1.14
  text "D10" at 55.46,28.645 h0.89
  text "5V" at 12.395,27.686 h1.5
  text "PWM" at 55.281,27.375 h1.14
  text "D9" at 56.155,26.308 h0.89
  text "GND" at 12.251,25.283 h1.5
  text "IO" at 56.618,25.181 h1.14
  text "D8" at 55.918,23.956 h1.02
  text "GND" at 12.395,22.606 h1.5
  text "IO" at 56.517,21.817 h1.14
  text "D7" at 55.88,20.508 h1.02
  text "VIN" at 12.395,20.066 h1.5
  text "PWM" at 55.246,18.777 h1.14
  text "D6" at 55.928,17.435 h1.02
  text "PWM" at 55.246,15.962 h1.14
  text "A0" at 12.395,14.986 h1.5
  text "D5" at 55.88,14.768 h1.02
  text "IO" at 56.617,13.542 h1.14
  text "A1" at 12.395,12.446 h1.5
  text "D4" at 55.867,12.292 h1.02
  text "PWM" at 55.246,10.856 h1.14
  text "L" at 47.57,10.225 h10.16
  text "A2" at 12.395,9.906 h1.5
  text "D3" at 55.88,9.561 h1.02
  text "IO" at 56.642,8.442 h1.14
  text "A3" at 12.395,7.366 h1.5
  text "D2" at 55.942,7.217 h1.02
  text "TX" at 56.314,5.954 h1.14
  text "A4" at 12.395,4.826 h1.5
  text "D1" at 56.315,4.76 h1.02
  text "RX" at 56.256,3.268 h1.14
  text "A5" at 12.395,2.286 h1.5
  text "J" at 45.542,2.15 h15
  text "D0" at 55.88,2.017 h1.02
  text "MB2046B" at 46.203,0.914 h2
  text "USER / USB" at 26.946,-1.198 h1.5 r90
  text "FDCAN" at 41.091,-1.215 h1.5 r90
  text ".Layer_Name" at -0.27,-24.55 h3
  text ".GTO" at 41.424,-24.55 h3
Bottom Overlay:
  text "H" at 28.855,50.325 h15
  text "SCL" at 57.404,48.26 h1.14
  text "D15" at 57.404,46.99 h1.02
  text "SDA" at 57.404,45.72 h1.14
  text "D14" at 57.404,44.45 h1.02
  text "I" at 27,42.63 h10
  text "AREF" at 57.404,42.418 h0.84
  text "GND" at 57.404,39.624 h1.02
  text "NC" at 14.224,38.1 h1.5
  text "SCK" at 57.404,38.1 h1.14
  text "D13" at 57.404,37.084 h0.89
  text "C" at 26.841,36.22 h7.5
  text "IOREF" at 16.256,35.56 h1.5
  text "MISO" at 57.404,35.56 h1.14
  text "D12" at 57.404,34.544 h0.89
  text "PWM" at 57.404,33.528 h1.14
  text "NRST" at 15.748,33.02 h1.5
  text "MOSI" at 57.404,32.766 h1.14
  text "D11" at 57.404,31.75 h0.89
  text "F" at 26.841,30.72 h9
  text "3V3" at 14.732,30.48 h1.5
  text "PWM" at 57.404,30.48 h1.14
  text "CS" at 57.404,29.718 h1.14
  text "D10" at 57.404,28.702 h0.89
  text "5V" at 13.97,27.94 h1.5
  text "PWM" at 57.404,27.432 h1.14
  text "D9" at 57.404,26.416 h0.89
  text "GND" at 15.24,25.4 h1.5
  text "G" at 27.091,25.22 h8
  text "IO" at 57.404,25.146 h1.14
  text "D8" at 57.404,23.876 h1.02
  text "GND" at 15.24,22.86 h1.5
  text "IO" at 57.404,21.336 h1.14
  text "VIN" at 14.478,20.32 h1.5
  text "D7" at 57.404,20.066 h1.02
  text "S" at 26.132,19.303 h7
  text "PWM" at 57.404,18.542 h1.14
  text "D6" at 57.404,17.272 h1.02
  text "PWM" at 57.404,16.002 h1.14
  text "A0" at 13.92,15.097 h1.5
  text "D5" at 57.404,14.732 h1.02
  text "E" at 26.591,13.72 h8
  text "IO" at 57.404,13.462 h1.14
  text "A1" at 13.92,12.557 h1.5
  text "D4" at 57.404,12.192 h1.02
  text "PWM" at 57.404,10.922 h1.14
  text "A2" at 13.92,10.017 h1.5
  text "D3" at 57.404,9.652 h1.02
  text "IO" at 57.404,8.382 h1.14
  text "A3" at 13.92,7.477 h1.5
  text "D2" at 57.404,7.112 h1.02
  text "TX" at 57.404,5.842 h1.14
  text "A4" at 13.92,4.937 h1.5
  text "D1" at 57.229,4.583 h1.02
  text "RX" at 57.404,3.048 h1.14
  text "A5" at 13.92,2.397 h1.5
  text "D0" at 57.404,1.778 h1.02
  text ".GBO" at 30.221,-24.582 h3
  text ".Layer_Name" at 71.535,-24.582 h3
Top Paste:
  text ".Layer_Name" at -0.298,-24.54 h3
  text ".GTP" at 41.397,-24.54 h3
Bottom Paste:
  text ".GBP" at 30.112,-24.567 h3
  text ".Layer_Name" at 71.426,-24.567 h3
Top Solder:
  region: 3.131,51.58 3.131,56.492 0.631,56.492 0.631,51.58
  text ".Layer_Name" at -0.273,-24.615 h3
  text ".GTS" at 41.422,-24.615 h3
Bottom Solder:
  region: 3.131,51.58 3.131,56.492 0.631,56.492 0.631,51.58
  text ".GBS" at 30.137,-24.642 h3
  text ".Layer_Name" at 71.451,-24.642 h3
M1-Board Shape:
  lines w0.1: 70.001,78.508 ccw(c68.001,78.508) 68.001,80.508 2.001,80.508 ccw(c2.001,78.508) 0.001,78.508 0.001,56.008 0.001,2.008 ccw(c2.001,2.008) 2.001,0.008 11.501,0.008 13.501,-1.992 46.501,-1.992 48.501,0.008 68.001,0.008 ccw(c68.001,2.008) 70.001,2.008 70.001,56.008 70.001,78.508 ; 70.001,78.508 70.001,78.508 ; 48.055,0.008 48.055,0.008
M2-Board Dimensions:
  text ".Layer_Name" at -0.27,-24.55 h3
  text ".GM2" at 41.424,-24.55 h3
M14-Top Assembly:
  text ".Layer_Name" at -0.27,-24.55 h3
  text ".GM14" at 41.424,-24.55 h3
M15-Bottom Assembly:
  text ".GM15" at 30.221,-24.582 h3
  text ".Layer_Name" at 71.535,-24.582 h3
M16-Top Courtyard:
  lines w0.149: 23.499,19.433 ccw(c23.999,19.433) 23.999,18.933 28.499,18.933 30.749,22.033 41.249,22.033 43.499,18.933 47.999,18.933 ccw(c47.999,19.433) 48.499,19.433 48.499,23.933 45.399,26.183 45.399,36.683 48.499,38.933 48.499,43.433 ccw(c47.999,43.433) 47.999,43.933 43.499,43.933 41.249,40.833 30.749,40.833 28.499,43.933 23.999,43.933 ccw(c23.999,43.433) 23.499,43.433 23.499,38.933 26.599,36.683 26.599,26.183 23.499,23.933 23.499,19.433
Drill Drawing:
  drawing of 413 lines, arcs and shapes, not listed
  text "« THE COMPONENTS WITH PLATED THROUGH HOLE (PTH) MAY BE WELDED (CABLED) IN \"PIN-IN-PASTE\" MODE (IF NECESSARY) »" at 16.926,134.883 h3.5
  text "PCB SPECIFICATIONS :" at 0.671,128.823 h3
  text "**Plating type :" at 117.721,128.473 h2.5
  text "Layer" at 149.446,124.937 h2
  text "Name" at 157.82,124.937 h2
  text "Material" at 174.017,124.937 h2
  text "Thickness" at 188.571,124.937 h2
  text "Constant" at 200.526,124.937 h2
  text "Board Layer Stack" at 211.59,124.937 h2
  text "A.   MATERIAL :" at 0.671,124.823 h3
  text "FR-4" at 39.171,124.823 h3
  text "TG-170" at 55.671,124.823 h3
  text "X  TG-150" at 73.921,124.823 h3
  text "TG-140" at 89.921,124.823 h3
  text "lead Gold" at 124.446,123.998 h2.5
  text "B.   MATERIAL FAMILY :" at 0.671,121.823 h3
  text "N/A" at 39.171,121.823 h3
  text "Top Overlay" at 157.82,120.937 h2
  text "C.   SOLDERMASK COLOR :" at 0.671,118.823 h3
  text "GREEN" at 39.171,118.823 h3
  text "X  WHITE" at 55.671,118.823 h3
  text "RED" at 73.921,118.823 h3
  text "BLACK" at 89.921,118.823 h3
  text "Top Solder" at 157.82,116.937 h2
  text "Solder Resist" at 174.017,116.937 h2
  text "0.015mm" at 188.571,116.937 h2
  text "3.5" at 200.526,116.937 h2
  text "D.   SILKSCREEN COLOR :" at 0.671,115.823 h3
  text "WHITE" at 39.171,115.823 h3
  text "YELLOW" at 55.671,115.823 h3
  text "BLACK" at 73.921,115.823 h3
  text "X  Blue ink PANTONE 2955" at 89.921,115.823 h3
  text "1" at 149.446,112.937 h2
  text "Top Layer" at 157.82,112.937 h2
  text "0.035mm" at 188.571,112.937 h2
  text "E.   SURFACE FINISH :" at 0.671,112.823 h3
  text "X  ENIG" at 39.171,112.823 h3
  text "IMMERSION SILVER" at 55.671,112.823 h3
  text "IMMERSION TIN" at 89.921,112.823 h3
  text "HASL" at 39.171,109.823 h3
  text "HASL (PB-FREE)" at 55.671,109.823 h3
  text "GOLDEN FINGER" at 89.921,109.823 h3
  text "Dielectric 1" at 157.82,108.937 h2
  text "1.400mm" at 188.571,108.937 h2
  text "4.2" at 200.526,108.937 h2
  text "F.   IMPEDANCE CONTROL :" at 0.671,106.823 h3
  text "NO" at 39.171,106.823 h3
  text "X  YES  (SEE IMPEDANCE TABLE FOR DETAIL INFORMATION)" at 55.671,106.823 h3
  text "2" at 149.445,104.937 h2
  text "Bottom Layer" at 157.82,104.937 h2
  text "0.035mm" at 188.571,104.937 h2
  text "G.   THROUGH VIA :" at 0.671,103.823 h3
  text "PLUG THE VIAS WHICH ARE COVERED WITH SOLDERMASK ONE OR TWO SIDE." at 39.171,103.823 h3
  text "Bottom Solder" at 157.82,100.937 h2
  text "Solder Resist" at 174.017,100.937 h2
  text "0.015mm" at 188.571,100.937 h2
  text "3.5" at 200.526,100.937 h2
  text "PLUG MATERIAL :" at 39.171,100.823 h3
  text "X  SOLDERMASK" at 64.671,100.823 h3
  text "NON-CONDUCTIVE EPOXY." at 89.921,100.823 h3
  text "H.   STACK-UP :" at 0.671,97.823 h3
  text "SEE LAYER STACK-UP SEQUENCE FOR OVERALL THICKNESS." at 39.171,97.823 h3
  text "Bottom Overlay" at 157.82,96.937 h2
  text "PCB : TYPE 3" at 83.195,89.283 h3
  text "MINIMUM PARAMETERS" at 124.511,89.098 h3
  text "ASPECT-RATIO, AXE Z :" at 83.195,83.783 h3
  text "DEFAULT" at 124.511,83.598 h3
  text "TRACKS : 0.1mm           / GAPS : 0.1mm" at 124.511,77.848 h3
  text "6:1 to 8:1 / LEVEL \"B\"" at 83.214,77.035 h3
  text "Symbol" at 84.124,70.466 h2.16
  text "Count" at 92.586,70.466 h2.16
  text "Hole Size" at 102.153,70.466 h2.16
  text "Plated" at 118.598,70.466 h2.16
  text "Hole Type" at 126.026,70.466 h2.16
  text "Drill Layer Pair" at 136.84,70.466 h2.16
  text "Via/Pad" at 157.339,70.466 h2.16
  text "Pad Shape" at 166.201,70.466 h2.16
  text "Template" at 177.777,70.466 h2.16
  text "Hole Length" at 194.72,70.466 h2.16
  text "Routed Path Length" at 210.27,70.466 h2.16
  text "2" at 92.586,66.738 h1.8
  text "0.65mm (25.59mil)" at 102.153,66.738 h1.8
  text "NPTH" at 118.598,66.738 h1.8
  text "Round" at 126.026,66.738 h1.8
  text "Top Layer - Bottom Layer" at 136.84,66.738 h1.8
  text "Pad" at 157.339,66.738 h1.8
  text "Rounded" at 166.201,66.738 h1.8
  text "c0hn65m5" at 177.777,66.738 h1.8
  text "-" at 194.72,66.738 h1.8
  text "-" at 210.27,66.738 h1.8
  text "2" at 92.586,63.01 h1.8
  text "0.65mm (25.59mil)" at 102.153,63.01 h1.8
  text "NPTH" at 118.598,63.01 h1.8
  text "Slot" at 126.026,63.01 h1.8
  text "Top Layer - Bottom Layer" at 136.84,63.01 h1.8
  text "Pad" at 157.339,63.01 h1.8
  text "Rounded" at 166.201,63.01 h1.8
  text "c0hn65_95m5" at 177.777,63.01 h1.8
  text "0.95mm (37.40mil)" at 194.72,63.01 h1.8
  text "0.30mm (11.81mil)" at 210.27,63.01 h1.8
  text "2" at 92.586,59.282 h1.8
  text "0.97mm (38.19mil)" at 102.153,59.282 h1.8
  text "NPTH" at 118.598,59.282 h1.8
  text "Round" at 126.026,59.282 h1.8
  text "Top Layer - Bottom Layer" at 136.84,59.282 h1.8
  text "Pad" at 157.339,59.282 h1.8
  text "Rounded" at 166.201,59.282 h1.8
  text "c0hn97m101" at 177.777,59.282 h1.8
  text "-" at 194.72,59.282 h1.8
  text "-" at 210.27,59.282 h1.8
  text "2" at 92.586,55.554 h1.8
  text "1.00mm (39.37mil)" at 102.153,55.554 h1.8
  text "NPTH" at 118.598,55.554 h1.8
  text "Round" at 126.026,55.554 h1.8
  text "Top Layer - Bottom Layer" at 136.84,55.554 h1.8
  text "Pad" at 157.339,55.554 h1.8
  text "Rounded" at 166.201,55.554 h1.8
  text "c50hn100m105" at 177.777,55.554 h1.8
  text "-" at 194.72,55.554 h1.8
  text "-" at 210.27,55.554 h1.8
  text "3" at 92.586,51.825 h1.8
  text "1.40mm (55.12mil)" at 102.153,51.825 h1.8
  text "PTH" at 118.598,51.825 h1.8
  text "Round" at 126.026,51.825 h1.8
  text "Top Layer - Bottom Layer" at 136.84,51.825 h1.8
  text "Pad" at 157.339,51.825 h1.8
  text "(Mixed)" at 166.201,51.825 h1.8
  text "(Mixed)" at 177.777,51.825 h1.8
  text "-" at 194.72,51.825 h1.8
  text "-" at 210.27,51.825 h1.8
  text "3" at 92.586,48.097 h1.8
  text "3.20mm (125.98mil)" at 102.153,48.097 h1.8
  text "NPTH" at 118.598,48.097 h1.8
  text "Round" at 126.026,48.097 h1.8
  text "Top Layer - Bottom Layer" at 136.84,48.097 h1.8
  text "Pad" at 157.339,48.097 h1.8
  text "Rounded" at 166.201,48.097 h1.8
  text "c320hn320" at 177.777,48.097 h1.8
  text "-" at 194.72,48.097 h1.8
  text "-" at 210.27,48.097 h1.8
  text "5" at 92.586,44.369 h1.8
  text "0.30mm (11.81mil)" at 102.153,44.369 h1.8
  text "PTH" at 118.598,44.369 h1.8
  text "Round" at 126.026,44.369 h1.8
  text "Top Layer - Bottom Layer" at 136.84,44.369 h1.8
  text "Via" at 157.339,44.369 h1.8
  text "Rounded" at 166.201,44.369 h1.8
  text "v50h30m0mx0" at 177.777,44.369 h1.8
  text "-" at 194.72,44.369 h1.8
  text "-" at 210.27,44.369 h1.8
  text "6" at 92.586,40.641 h1.8
  text "0.30mm (11.81mil)" at 102.153,40.641 h1.8
  text "PTH" at 118.598,40.641 h1.8
  text "Round" at 126.026,40.641 h1.8
  text "Top Layer - Bottom Layer" at 136.84,40.641 h1.8
  text "Via" at 157.339,40.641 h1.8
  text "Rounded" at 166.201,40.641 h1.8
  text "v50h30m0mx0(Tol0)" at 177.777,40.641 h1.8
  text "-" at 194.72,40.641 h1.8
  text "-" at 210.27,40.641 h1.8
  text "8" at 92.586,36.913 h1.8
  text "0.50mm (19.69mil)" at 102.153,36.913 h1.8
  text "PTH" at 118.598,36.913 h1.8
  text "Slot" at 126.026,36.913 h1.8
  text "Top Layer - Bottom Layer" at 136.84,36.913 h1.8
  text "Pad" at 157.339,36.913 h1.8
  text "Rounded" at 166.201,36.913 h1.8
  text "(Mixed)" at 177.777,36.913 h1.8
  text "1.10mm (43.31mil)" at 194.72,36.913 h1.8
  text "0.60mm (23.62mil)" at 210.27,36.913 h1.8
  text "21" at 92.586,33.184 h1.8
  text "0.40mm (15.75mil)" at 102.153,33.184 h1.8
  text "PTH" at 118.598,33.184 h1.8
  text "Round" at 126.026,33.184 h1.8
  text "Top Layer - Bottom Layer" at 136.84,33.184 h1.8
  text "Via" at 157.339,33.184 h1.8
  text "Rounded" at 166.201,33.184 h1.8
  text "v70h40m0mx0(Tol0)" at 177.777,33.184 h1.8
  text "-" at 194.72,33.184 h1.8
  text "-" at 210.27,33.184 h1.8
  text "32" at 92.586,29.456 h1.8
  text "1.10mm (43.31mil)" at 102.153,29.456 h1.8
  text "PTH" at 118.598,29.456 h1.8
  text "Round" at 126.026,29.456 h1.8
  text "Top Layer - Bottom Layer" at 136.84,29.456 h1.8
  text "Pad" at 157.339,29.456 h1.8
  text "Rounded" at 166.201,29.456 h1.8
  text "(Mixed)" at 177.777,29.456 h1.8
  text "-" at 194.72,29.456 h1.8
  text "-" at 210.27,29.456 h1.8
  text "110" at 92.586,25.728 h1.8
  text "1.00mm (39.37mil)" at 102.153,25.728 h1.8
  text "PTH" at 118.598,25.728 h1.8
  text "Round" at 126.026,25.728 h1.8
  text "Top Layer - Bottom Layer" at 136.84,25.728 h1.8
  text "Pad" at 157.339,25.728 h1.8
  text "Rounded" at 166.201,25.728 h1.8
  text "(Mixed)" at 177.777,25.728 h1.8
  text "-" at 194.72,25.728 h1.8
  text "-" at 210.27,25.728 h1.8
  text "184" at 92.586,22 h1.8
  text "0.25mm (9.84mil)" at 102.153,22 h1.8
  text "PTH" at 118.598,22 h1.8
  text "Round" at 126.026,22 h1.8
  text "Top Layer - Bottom Layer" at 136.84,22 h1.8
  text "Via" at 157.339,22 h1.8
  text "Rounded" at 166.201,22 h1.8
  text "v45h25m0mx0" at 177.777,22 h1.8
  text "-" at 194.72,22 h1.8
  text "-" at 210.27,22 h1.8
  text "646" at 92.586,18.271 h1.8
  text "0.25mm (9.84mil)" at 102.153,18.271 h1.8
  text "PTH" at 118.598,18.271 h1.8
  text "Round" at 126.026,18.271 h1.8
  text "Top Layer - Bottom Layer" at 136.84,18.271 h1.8
  text "Via" at 157.339,18.271 h1.8
  text "Rounded" at 166.201,18.271 h1.8
  text "v45h25m0mx0(Tol0)" at 177.777,18.271 h1.8
  text "-" at 194.72,18.271 h1.8
  text "-" at 210.27,18.271 h1.8
  text "1026 Total" at 92.586,14.543 h1.8
  text "Slot definitions :" at 84.124,11.933 h1.8
  text "Routed Path Length" at 96.41,11.933 h1.8
  text "= Calculated from tool start centre position to tool end centre position." at 111.63,11.933 h1.8
  text "Hole Length" at 96.41,10.442 h1.8
  text "= Routed Path Length + Tool Size = Slot length as defined in the PCB layout" at 105.979,10.442 h1.8
  text "IMPEDANCE TABLE   USB HS STLINK" at 83.069,4.655 h3
  text "LAYER" at 87.319,-0.345 h3
  text "TRACE" at 103.569,-0.345 h3
  text "SPACING" at 114.069,-0.345 h3
  text "IMPEDANCE" at 127.569,-0.345 h3
  text "IMPEDANCE" at 144.569,-0.345 h3
  text "TOL." at 163.319,-0.345 h3
  text "(mm)" at 117.394,-2.82 h2.5
  text "(mm)" at 105.569,-2.87 h2.5
  text "(Single ended)" at 128.069,-3.095 h2.5
  text "(Differential)" at 145.819,-3.095 h2.5
  text "+/- 15%" at 162.374,-6.735 h3
  text "0.3" at 104.544,-6.82 h3
  text "TOP" at 83.549,-6.86 h3
  text "0.134" at 116.569,-6.845 h3
  text "n/a" at 130.924,-6.91 h3
  text "90 ohm" at 147.01,-7.086 h3
  text ".Layer_Name" at -0.27,-24.55 h3
  text ".DRL" at 41.424,-24.55 h3
M20-Top Sheet Box:
  circle w0.254: c77.734,-31.271 r1.3
  region: 77.259,-24.034 61.732,-24.034 61.038,-25.81 59.827,-27.035 58.43,-25.175 58.43,-23.524 59.573,-22.127 61.009,-21.748 77.259,-21.748
  region: 63.256,-32.364 52.5,-32.364 53.493,-29.871 61.351,-29.871 61.8,-29.112 64.008,-31.66
  lines w0.254: 53.493,-29.871 62.285,-29.871 59.219,-26.333 cw(c61.023,-24.389) 61.263,-21.748 78.027,-21.748 77.265,-24.034 ; 56.807,-21.501 cw(c59.233,-22.472) 59.47,-19.869 ; 56.846,-21.469 52.5,-32.364 71.822,-32.364 ccw(c72.071,-29.629) 74.62,-30.649 ; 58.586,-25.403 64.008,-31.66 ; 58.84,-25.403 64.145,-31.525 ; 58.84,-25.149 64.145,-31.271 ; 58.938,-24.034 71.931,-24.034 ; 58.967,-25.022 64.272,-31.144 ; 59.094,-24.895 64.399,-31.017 ; 59.221,-24.768 64.526,-30.89 ; 59.348,-24.641 64.653,-30.763 ; 59.403,-22.689 64.708,-28.81 ; 59.471,-19.869 78.92,-19.869 74.621,-30.647 ; 59.475,-24.514 64.725,-30.573 ; 59.475,-24.26 64.78,-30.382 ; 59.475,-24.006 64.78,-30.128 ; 59.475,-23.117 64.78,-29.239 ; 59.602,-23.879 64.907,-30.001 ; 59.602,-23.498 64.907,-29.62 ; 60.973,-29.884 ccw(c61.079,-29.349) 61.376,-28.892 ; 62.06,-24.021 ccw(c62.034,-24.588) 61.704,-25.05 64.069,-27.779 cw(c62.265,-29.723) 62.997,-32.271 ; 68.341,-32.16 71.231,-23.78 ; 68.564,-32.11 71.433,-23.789 ; 68.691,-32.11 71.56,-23.789 ; 68.945,-32.11 71.814,-23.789 ; 69.199,-32.11 72.068,-23.789 ; 69.453,-32.11 72.322,-23.789 ; 69.707,-32.11 72.576,-23.789 ; 69.961,-32.11 72.83,-23.789 ; 70.215,-32.11 73.084,-23.789 ; 70.469,-32.11 73.338,-23.789 ; 70.677,-32.16 73.567,-23.78 ; 73.567,-24.034 77.259,-24.034 ; 76.591,-24.032 77.353,-21.746 ; 76.757,-24.034 77.519,-21.748 ; 77.011,-24.034 77.773,-21.748
  lines w0.3: -9.271,-31.25 50.729,-31.25 ; -9.271,-26.25 50.729,-26.25 ; -9.271,-21.25 50.729,-21.25 ; 30.729,-36.25 30.729,-21.25 ; 50.729,-36.25 50.729,-16.25 ; 68.341,-32.16 70.677,-32.16 ; -9.27,-36.25 -9.27,-16.25 80.729,-16.25 80.729,-36.25 -9.271,-36.25
  text "Project: '.Board_Name'" at -8.27,-19.466 h3
  text "Layer:" at -8.27,-24.55 h3
  text "Gerber:" at 31.718,-24.55 h3
  text "Variant: '.VariantName'" at -8.27,-29.55 h3
  text "'.Board_Reference'" at 31.845,-29.55 h3
  text "R" at 77.226,-32.033 h1.52
  text "Date: '.Board_Document_Date'" at -8.27,-34.55 h3
  text "Rev: '.Board_PCB_Revision'" at 31.788,-34.55 h3
M21-Bottom Sheet Box:
  circle w0.254: c-6.088,-31.271 r1.3
  region: 8.39,-32.364 19.146,-32.364 18.153,-29.871 10.295,-29.871 9.847,-29.112 7.638,-31.66
  region: -5.613,-24.034 9.914,-24.034 10.609,-25.81 11.819,-27.035 13.216,-25.175 13.216,-23.524 12.073,-22.127 10.637,-21.748 -5.613,-21.748
  lines w0.254: -6.127,-21.748 -5.365,-24.034 ; -5.873,-21.748 -5.111,-24.034 ; -5.707,-21.746 -4.945,-24.032 ; -5.619,-24.034 -6.381,-21.748 10.383,-21.748 cw(c10.623,-24.389) 12.427,-26.333 9.361,-29.871 18.153,-29.871 ; -5.613,-24.034 -1.921,-24.034 ; -2.975,-30.647 -7.274,-19.869 12.175,-19.869 ; -2.974,-30.649 ccw(c-0.425,-29.629) -0.176,-32.364 19.146,-32.364 14.8,-21.469 ; -1.921,-23.78 0.969,-32.16 ; -1.692,-23.789 1.177,-32.11 ; -1.438,-23.789 1.431,-32.11 ; -1.184,-23.789 1.685,-32.11 ; -0.93,-23.789 1.939,-32.11 ; -0.676,-23.789 2.193,-32.11 ; -0.422,-23.789 2.447,-32.11 ; -0.285,-24.034 12.708,-24.034 ; -0.168,-23.789 2.701,-32.11 ; 0.086,-23.789 2.955,-32.11 ; 0.213,-23.789 3.082,-32.11 ; 0.415,-23.78 3.305,-32.16 ; 6.739,-30.001 12.044,-23.879 ; 6.739,-29.62 12.044,-23.498 ; 6.866,-30.382 12.171,-24.26 ; 6.866,-30.128 12.171,-24.006 ; 6.866,-29.239 12.171,-23.117 ; 6.921,-30.573 12.171,-24.514 ; 6.939,-28.81 12.244,-22.689 ; 6.993,-30.763 12.298,-24.641 ; 7.12,-30.89 12.425,-24.768 ; 7.247,-31.017 12.552,-24.895 ; 7.374,-31.144 12.679,-25.022 ; 7.501,-31.525 12.806,-25.403 ; 7.501,-31.271 12.806,-25.149 ; 7.638,-31.66 13.06,-25.403 ; 8.649,-32.271 cw(c9.381,-29.723) 7.577,-27.779 9.942,-25.05 ccw(c9.612,-24.588) 9.586,-24.021 ; 10.27,-28.892 ccw(c10.568,-29.349) 10.673,-29.884 ; 12.177,-19.869 cw(c12.413,-22.472) 14.839,-21.501
  lines w0.3: 0.969,-32.16 3.305,-32.16 ; 20.729,-36.25 20.729,-16.25 ; 20.729,-31.25 80.729,-31.25 ; 20.729,-26.25 80.729,-26.25 ; 20.729,-21.25 80.729,-21.25 ; 40.729,-36.25 40.729,-21.25 ; -9.271,-36.25 80.729,-36.25 80.729,-16.25 -9.271,-16.25 -9.271,-36.25
  text "Project: '.Board_Name'" at 79.535,-19.466 h3
  text "Gerber:" at 39.547,-24.55 h3
  text "Layer:" at 79.535,-24.55 h3
  text "'.Board_Reference'" at 39.547,-29.55 h3
  text "Variant: '.VariantName'" at 79.535,-29.55 h3
  text "R" at -5.58,-32.033 h1.52
  text "Rev: '.Board_PCB_Revision'" at 39.604,-34.55 h3
  text "Date: '.Board_Document_Date'" at 79.535,-34.55 h3

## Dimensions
43.891,0.508 to 0.001,2.008 on M2-Board Dimensions
43.891,0.508 to 70.001,2.008 on M2-Board Dimensions
59.131,51.308 to 68.001,80.508 on M2-Board Dimensions
0.001,78.508 to 10.871,52.578 on M2-Board Dimensions
10.871,52.578 to 59.131,51.308 on M2-Board Dimensions
59.131,51.308 to 64.211,48.768 on M2-Board Dimensions
3.251,48.768 to 10.871,52.578 on M2-Board Dimensions
3.251,3.048 to 66.751,3.048 on M2-Board Dimensions
59.131,51.308 to 43.891,0.508 on M2-Board Dimensions
10.871,52.578 to 43.891,0.508 on M2-Board Dimensions
10.871,52.578 to 2.001,80.508 on M2-Board Dimensions
59.131,51.308 to 70.001,78.508 on M2-Board Dimensions
2.001,80.508 to 13.501,-1.992 on M2-Board Dimensions
0.001,78.508 to 70.001,78.508 on M2-Board Dimensions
